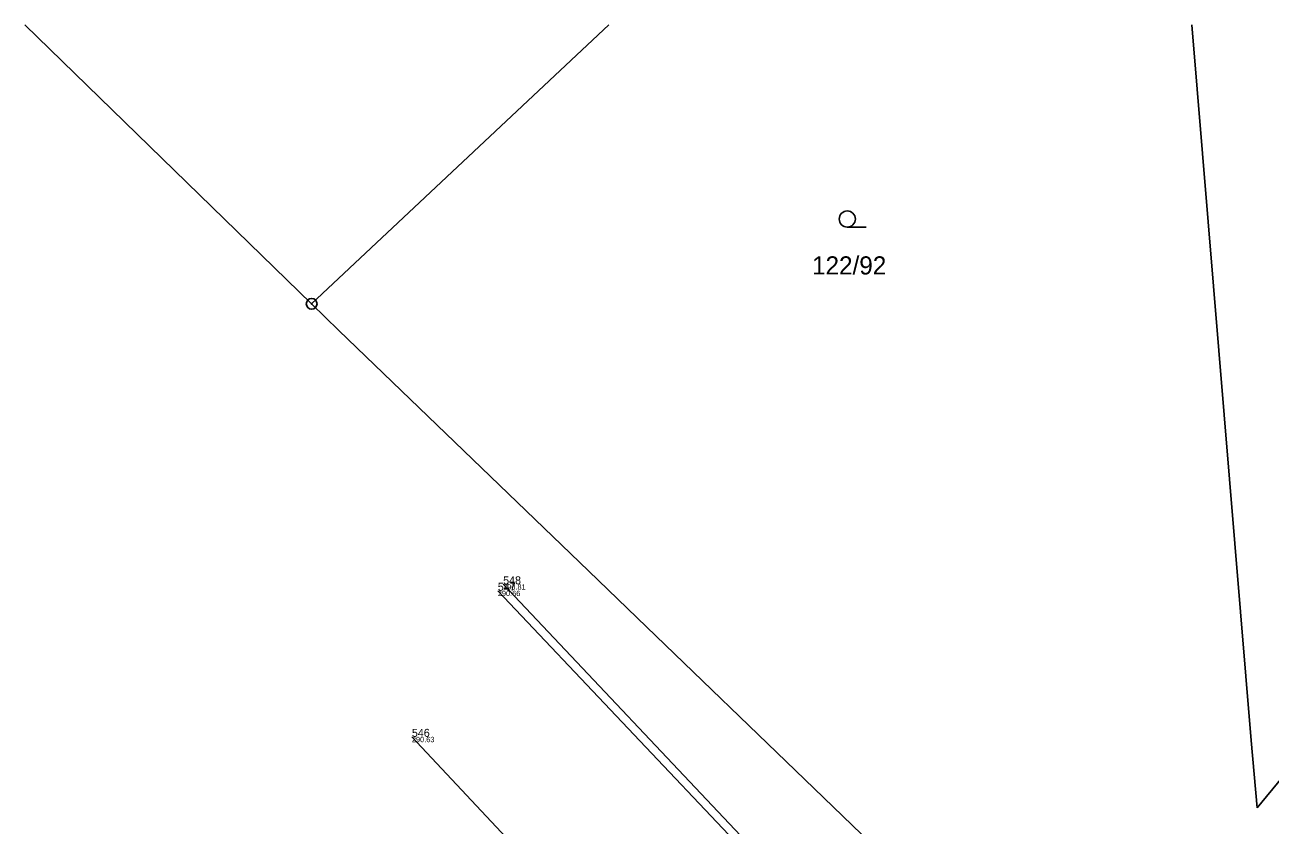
# Model space of a CAD drawing. Extents: x -805057 to -804930, y -994399 to -994240.
# Drawn here: x -805023.19 to -804999.86, y -994258.18 to -994243.17 of the extents above; entities that cross this region are included whole.
import ezdxf

# ---------------------------------------------------------------- set-up
doc = ezdxf.new("R2010")
doc.units = 0
for name, color, linetype in [('bod cislo', 7, 'Continuous'), ('bod pozice', 7, 'Continuous'), ('bod výška', 7, 'Continuous'), ('Katastralni mapa', 7, 'Continuous'), ('komunikace', 7, 'Continuous')]:
    doc.layers.add(name, color=color, linetype=linetype)

msp = doc.modelspace()

# ---------------------------------------------------------------- linework, layer by layer
at = {"layer": 'bod pozice'}
for p, q in [((-805014.23, -994253.66), (-805014.23, -994253.66)), ((-805014.33, -994253.78), (-805014.33, -994253.78)), ((-805015.94, -994256.52), (-805015.94, -994256.52))]:
    msp.add_line(p, q, dxfattribs=at)
at = {"layer": 'Katastralni mapa'}
for points in [[(-805023.193, -994243.17), (-805017.82, -994248.4)], [(-805017.82, -994248.4), (-805012.246, -994243.17)], [(-805001.32, -994243.17), (-805000.21, -994256.59)], [(-805007.78, -994246.96), (-805007.429, -994246.96)], [(-805017.82, -994248.4), (-805017.31, -994248.9)], [(-805017.31, -994248.9), (-805012.63, -994253.41)], [(-805000.1, -994257.85), (-804995.97, -994252.84)], [(-805012.63, -994253.41), (-805011.72, -994254.29)], [(-805011.72, -994254.29), (-805008.4, -994257.49)], [(-805000.21, -994256.59), (-805000.1, -994257.85)], [(-805008.4, -994257.49), (-805003.78, -994261.95)]]:
    msp.add_lwpolyline(points, dxfattribs=at)
for centre, radius in [((-805007.78, -994246.81), 0.151), ((-805017.819, -994248.4), 0.101), ((-805017.819, -994248.4), 0.00652)]:
    msp.add_circle(centre, radius, dxfattribs=at)
at = {"layer": 'komunikace'}
for p, q in [((-804993.27, -994275.83), (-805014.23, -994253.66)), ((-805014.33, -994253.78), (-804993.36, -994275.93)), ((-805005.75, -994267.39), (-805015.94, -994256.52))]:
    msp.add_line(p, q, dxfattribs=at)

# ---------------------------------------------------------------- texts
at = {"layer": 'bod cislo'}
for s, p in [('547    ', (-805014.33, -994253.78)), ('548    ', (-805014.23, -994253.66)), ('546    ', (-805015.94, -994256.52))]:
    msp.add_text(s, height=0.15, dxfattribs=at).set_placement(p)
at = {"layer": 'bod výška'}
for s, p in [('290.81  ', (-805014.23, -994253.76)), ('290.66  ', (-805014.33, -994253.88)), ('290.63  ', (-805015.94, -994256.62))]:
    msp.add_text(s, height=0.1, dxfattribs=at).set_placement(p)
at = {"layer": 'Katastralni mapa'}
msp.add_text('122/92', height=0.34, dxfattribs=at).set_placement((-805008.44, -994247.85))

doc.saveas('drawing.dxf')
